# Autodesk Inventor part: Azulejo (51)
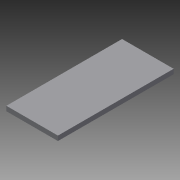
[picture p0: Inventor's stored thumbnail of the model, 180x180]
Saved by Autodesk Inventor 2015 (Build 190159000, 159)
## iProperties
Created: 2015-04
Part Number: Azulejo (51)
Material: Genérico
Document SubType Name: Modeling
Designer: Felipe
Density: 1 g/cm^3
Appearance: Padrão
Author: Felipe
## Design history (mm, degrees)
sketch "Sketch1"
  geometry: L1 (331.131, 3802.232)-(331.131, 2322.232); L2 (-328.869, 3802.232)-(331.131, 3802.232); L3 (-328.869, 2322.232)-(331.131, 2322.232); L4 (-328.869, -3617.768)-(-328.869, 3802.232); 1 further point
  constraints: 8 end point, 1 point on line
  dimensions: "d2" = 660 distance between parallel lines of L1 L4; "d3" = 1480 distance between parallel lines of L2 L3
extrude "Extrusion1" new body sketch "Sketch1" distance "d0" = 60; taper "d1" = 0 deg
body "Solid1"
